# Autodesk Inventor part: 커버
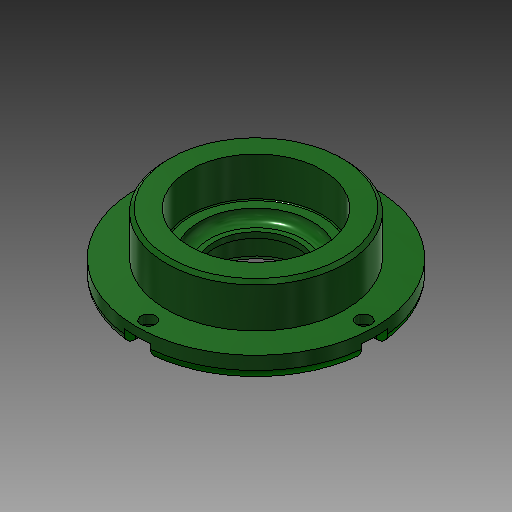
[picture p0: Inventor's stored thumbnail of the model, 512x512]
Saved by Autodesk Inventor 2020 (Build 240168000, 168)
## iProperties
Created: 2016-04
Part Number: 커버
Document SubType Name: Modeling
Designer: mdu
Density: 7.86 g/cm^3
Mass: 351.567 g
Surface Area: 161.165 cm^2
Volume: 44.7286 cm^3
Material: 강철, 연강
Appearance: 진녹색
Company: 한국ATC센터
Author: mdu
Revision Number: 1
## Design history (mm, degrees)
sketch "스케치1"
  geometry: C1 r 36 at (0, 0); 1 further point
  constraints: 1 centre point, 1 coincident
  dimensions: "d0" = 72 diameter of C1
extrude "돌출1" new body sketch "스케치1" distance "d1" = 7; taper "d2" = 0 deg
sketch "스케치2"
  geometry: C1 r 27 at (0, 0); 1 further point
  constraints: 1 centre point, 1 coincident
  dimensions: "d3" = 54 diameter of C1
extrude "돌출2" join sketch "스케치2" distance "d4" = 13; taper "d5" = 0 deg
sketch "스케치3"
  geometry: C1 r 20 at (0, 0); 1 further point
  constraints: 1 centre point, 1 coincident
  dimensions: "d6" = 40 diameter of C1
extrude "돌출3" join sketch "스케치3" distance "d7" = 5; taper "d8" = 0 deg
hole "구멍1" diameter "d11" = 25; stored, may be unused: countersink angle "d15" = 90 deg, drill point angle "d17" = 118 deg; dims "d9" = 10, "d10" = 10, "d12" = 6, "d13" = 32, "d14" = 8.3, "d16" = 8
hole "구멍2" diameter "d20" = 34; stored, may be unused: countersink angle "d24" = 90 deg, drill point angle "d26" = 0 deg; dims "d18" = 10, "d19" = 10, "d21" = 6, "d22" = 40, "d23" = 12, "d25" = 3
fillet "모깎기2" dims "d34" = 3
fillet "모깎기1" dims "d27" = 0.3
chamfer "모따기1" distance "d28" = 1; stored, may be unused: second distance "d29" = 2, angle "d30" = 45 deg
chamfer "모따기2" distance "d31" = 1.2; stored, may be unused: second distance "d32" = 2, angle "d33" = 30 deg
sketch "스케치4" dims "d35" = 65
  geometry: 3 further points
  constraints: 2 horizontal alignment, 1 coincident, 2 other
hole "구멍3" sketch "스케치4" at (32.5, 0) diameter "d36" = 4.5; stored, may be unused: countersink angle "d40" = 90 deg, drill point angle "d42" = 118 deg; dims "d37" = 6, "d38" = 8, "d39" = 4.4, "d41" = 13
sketch "스케치5"
  geometry: L1 (4, 0)-(4, 3.5); L2 (-4, 3.5)-(-4, 0); L3 (4, 3.5)-(-4, 3.5); C1 r 2.25 at (0, 0) reference; C2 r 36 at (0, -32.5) reference; A1 r 4 centre (0, 0) between (-2.037, 3.442) and (2.037, 3.442) reference; A2 r 36 centre (0, -32.5) between (2.037, 3.442) and (-2.037, 3.442) reference; 2 further points
  constraints: 6 end point, 2 horizontal alignment, 2 point on circle, 1 horizontal, 1 midpoint, 1 parallel, 1 tangent, 1 vertical, 1 vertical alignment
extrude "돌출4" cut sketch "스케치5" extent not by distance; stored distance "d47" = 24.5; taper "d48" = 0 deg
node "솔리드1"
pattern_circular "원형 패턴1" dims angle "d44" = 360 deg
pattern_circular "원형 패턴2" dims angle "d50" = 360 deg
node "투영된 루프1"
